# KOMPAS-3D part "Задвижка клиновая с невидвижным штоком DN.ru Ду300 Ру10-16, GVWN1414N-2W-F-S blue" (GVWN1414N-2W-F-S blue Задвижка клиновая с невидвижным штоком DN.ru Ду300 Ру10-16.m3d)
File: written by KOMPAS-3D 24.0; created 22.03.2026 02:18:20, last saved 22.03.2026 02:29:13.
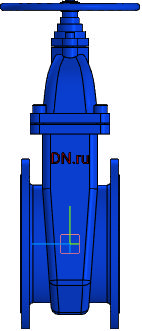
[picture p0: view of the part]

Document properties: Автор: R2D2; Полное имя файла: GVWN1414N-2W-F-S blue Задвижка клиновая с невидвижным штоком DN.ru Ду300 Ру10-16.cdw

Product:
- Part/product: Задвижка клиновая с невидвижным штоком DN.ru Ду300 Ру10-16  | designation GVWN1414N-2W-F-S blue
    Масса: 100
    Раздел спецификации: Прочие изделия
    Форматы листов документа: A2
    Примечание: D040-10587

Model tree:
1. Операция без истории:2

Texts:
  GVWN1414N-2W-F-S blue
